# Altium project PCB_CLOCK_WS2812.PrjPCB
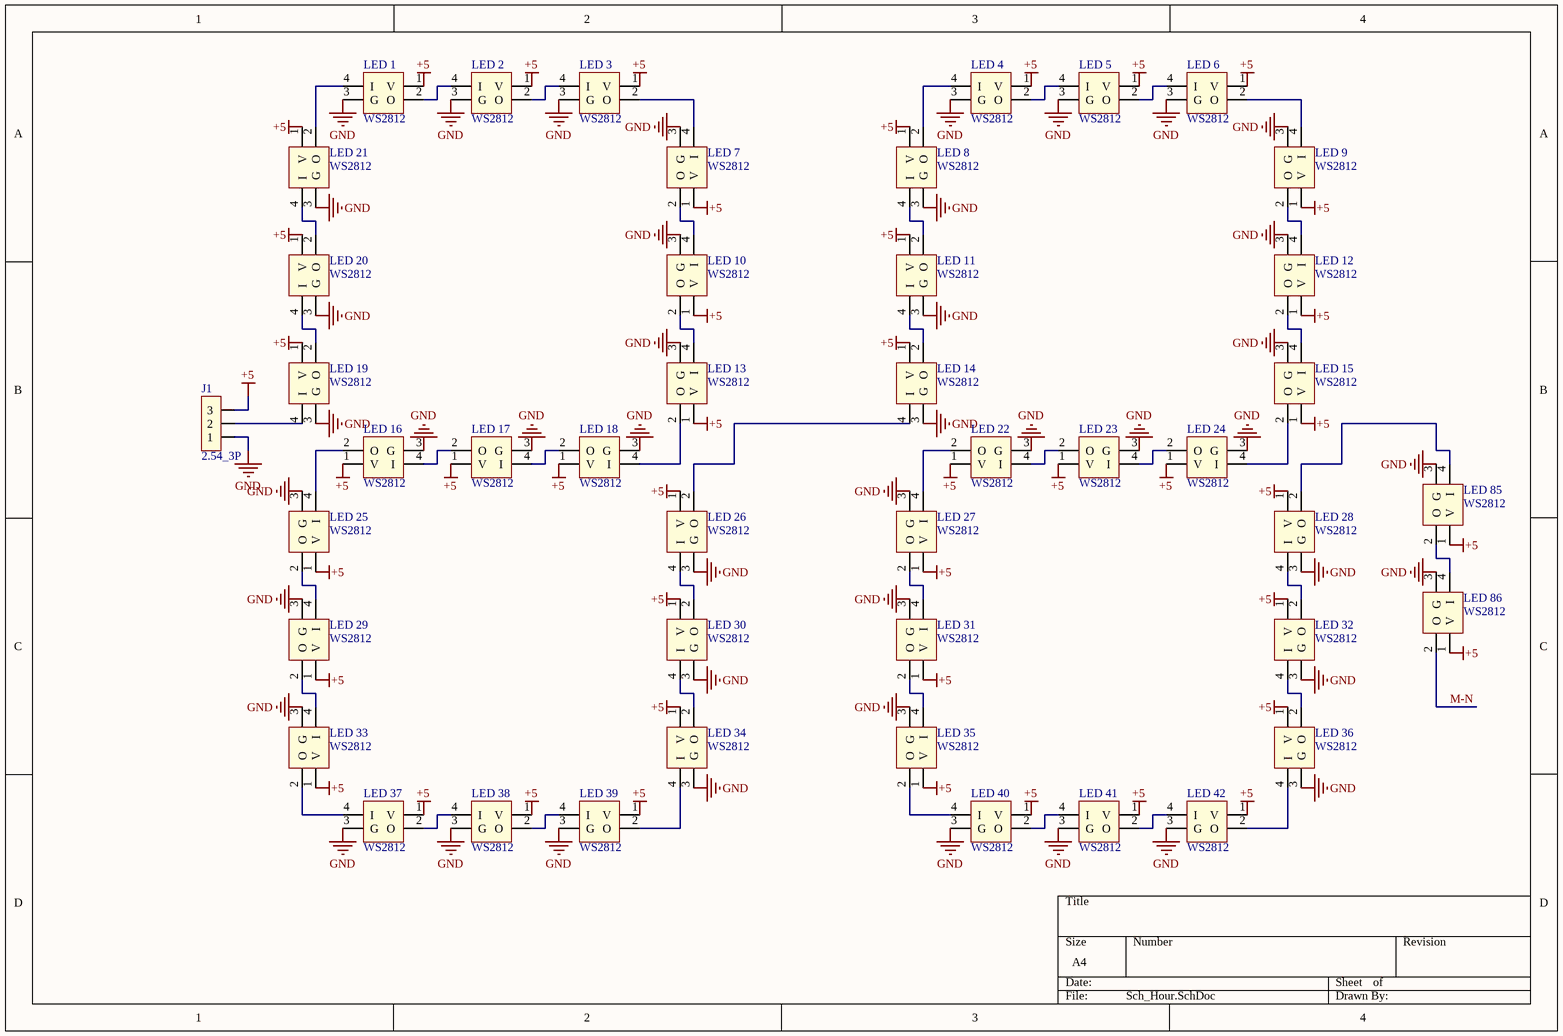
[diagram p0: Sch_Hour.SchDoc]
2 sheets, 88 parts. Net scope: global (net labels, ports and power ports of the same name join across sheets).
Board file: Clock WS2812.PcbDoc
Sheets:
  Sch_Hour.SchDoc
  Sch_Min.SchDoc

## Sheet Sch_Hour.SchDoc
size A4

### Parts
J1  2.54_3P  [jump don duc thang 2.54_3p]
LED_1  WS2812  [LED WS2812]
LED_2  WS2812  [LED WS2812]
LED_3  WS2812  [LED WS2812]
LED_4  WS2812  [LED WS2812]
LED_5  WS2812  [LED WS2812]
LED_6  WS2812  [LED WS2812]
LED_7  WS2812  [LED WS2812]
LED_8  WS2812  [LED WS2812]
LED_9  WS2812  [LED WS2812]
LED_10  WS2812  [LED WS2812]
LED_11  WS2812  [LED WS2812]
LED_12  WS2812  [LED WS2812]
LED_13  WS2812  [LED WS2812]
LED_14  WS2812  [LED WS2812]
LED_15  WS2812  [LED WS2812]
LED_16  WS2812  [LED WS2812]
LED_17  WS2812  [LED WS2812]
LED_18  WS2812  [LED WS2812]
LED_19  WS2812  [LED WS2812]
LED_20  WS2812  [LED WS2812]
LED_21  WS2812  [LED WS2812]
LED_22  WS2812  [LED WS2812]
LED_23  WS2812  [LED WS2812]
LED_24  WS2812  [LED WS2812]
LED_25  WS2812  [LED WS2812]
LED_26  WS2812  [LED WS2812]
LED_27  WS2812  [LED WS2812]
LED_28  WS2812  [LED WS2812]
LED_29  WS2812  [LED WS2812]
LED_30  WS2812  [LED WS2812]
LED_31  WS2812  [LED WS2812]
LED_32  WS2812  [LED WS2812]
LED_33  WS2812  [LED WS2812]
LED_34  WS2812  [LED WS2812]
LED_35  WS2812  [LED WS2812]
LED_36  WS2812  [LED WS2812]
LED_37  WS2812  [LED WS2812]
LED_38  WS2812  [LED WS2812]
LED_39  WS2812  [LED WS2812]
LED_40  WS2812  [LED WS2812]
LED_41  WS2812  [LED WS2812]
LED_42  WS2812  [LED WS2812]
LED_85  WS2812  [LED WS2812]
LED_86  WS2812  [LED WS2812]

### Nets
+5: J1.3 LED_1.1(V) LED_2.1(V) LED_3.1(V) LED_4.1(V) LED_5.1(V) LED_6.1(V) LED_7.1(V) LED_8.1(V) LED_9.1(V) LED_10.1(V) LED_11.1(V) LED_12.1(V) LED_13.1(V) LED_14.1(V) LED_15.1(V) LED_16.1(V) LED_17.1(V) LED_18.1(V) LED_19.1(V) LED_20.1(V) LED_21.1(V) LED_22.1(V) LED_23.1(V) LED_24.1(V) LED_25.1(V) LED_26.1(V) LED_27.1(V) LED_28.1(V) LED_29.1(V) LED_30.1(V) LED_31.1(V) LED_32.1(V) LED_33.1(V) LED_34.1(V) LED_35.1(V) LED_36.1(V) LED_37.1(V) LED_38.1(V) LED_39.1(V) LED_40.1(V) LED_41.1(V) LED_42.1(V) LED_85.1(V) LED_86.1(V)
GND: J1.1 LED_1.3(G) LED_2.3(G) LED_3.3(G) LED_4.3(G) LED_5.3(G) LED_6.3(G) LED_7.3(G) LED_8.3(G) LED_9.3(G) LED_10.3(G) LED_11.3(G) LED_12.3(G) LED_13.3(G) LED_14.3(G) LED_15.3(G) LED_16.3(G) LED_17.3(G) LED_18.3(G) LED_19.3(G) LED_20.3(G) LED_21.3(G) LED_22.3(G) LED_23.3(G) LED_24.3(G) LED_25.3(G) LED_26.3(G) LED_27.3(G) LED_28.3(G) LED_29.3(G) LED_30.3(G) LED_31.3(G) LED_32.3(G) LED_33.3(G) LED_34.3(G) LED_35.3(G) LED_36.3(G) LED_37.3(G) LED_38.3(G) LED_39.3(G) LED_40.3(G) LED_41.3(G) LED_42.3(G) LED_85.3(G) LED_86.3(G)
M-N: LED_86.2(O)
NetJ1_2: J1.2 LED_19.4(I)
NetLED_1_2: LED_1.2(O) LED_2.4(I)
NetLED_1_4: LED_1.4(I) LED_21.2(O)
NetLED_2_2: LED_2.2(O) LED_3.4(I)
NetLED_3_2: LED_3.2(O) LED_7.4(I)
NetLED_4_2: LED_4.2(O) LED_5.4(I)
NetLED_4_4: LED_4.4(I) LED_8.2(O)
NetLED_5_2: LED_5.2(O) LED_6.4(I)
NetLED_6_2: LED_6.2(O) LED_9.4(I)
NetLED_7_2: LED_7.2(O) LED_10.4(I)
NetLED_8_4: LED_8.4(I) LED_11.2(O)
NetLED_9_2: LED_9.2(O) LED_12.4(I)
NetLED_10_2: LED_10.2(O) LED_13.4(I)
NetLED_11_4: LED_11.4(I) LED_14.2(O)
NetLED_12_2: LED_12.2(O) LED_15.4(I)
NetLED_13_2: LED_13.2(O) LED_18.4(I)
NetLED_14_4: LED_14.4(I) LED_26.2(O)
NetLED_15_2: LED_15.2(O) LED_24.4(I)
NetLED_16_2: LED_16.2(O) LED_25.4(I)
NetLED_16_4: LED_16.4(I) LED_17.2(O)
NetLED_17_4: LED_17.4(I) LED_18.2(O)
NetLED_19_2: LED_19.2(O) LED_20.4(I)
NetLED_20_2: LED_20.2(O) LED_21.4(I)
NetLED_22_2: LED_22.2(O) LED_27.4(I)
NetLED_22_4: LED_22.4(I) LED_23.2(O)
NetLED_23_4: LED_23.4(I) LED_24.2(O)
NetLED_25_2: LED_25.2(O) LED_29.4(I)
NetLED_26_4: LED_26.4(I) LED_30.2(O)
NetLED_27_2: LED_27.2(O) LED_31.4(I)
NetLED_28_2: LED_28.2(O) LED_85.4(I)
NetLED_28_4: LED_28.4(I) LED_32.2(O)
NetLED_29_2: LED_29.2(O) LED_33.4(I)
NetLED_30_4: LED_30.4(I) LED_34.2(O)
NetLED_31_2: LED_31.2(O) LED_35.4(I)
NetLED_32_4: LED_32.4(I) LED_36.2(O)
NetLED_33_2: LED_33.2(O) LED_37.4(I)
NetLED_34_4: LED_34.4(I) LED_39.2(O)
NetLED_35_2: LED_35.2(O) LED_40.4(I)
NetLED_36_4: LED_36.4(I) LED_42.2(O)
NetLED_37_2: LED_37.2(O) LED_38.4(I)
NetLED_38_2: LED_38.2(O) LED_39.4(I)
NetLED_40_2: LED_40.2(O) LED_41.4(I)
NetLED_41_2: LED_41.2(O) LED_42.4(I)
NetLED_85_2: LED_85.2(O) LED_86.4(I)

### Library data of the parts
J1 = Jump Don Duc Thang 2.54_3P: Cắm; Ten_Linh_Kien: Jump Đơn Đực 2.54MM 1x40P Thẳng 11MM; Ma_Hang: MH000903; Don_Vi: Con; So_Chan: 2
LED_1-LED_42 LED_85 LED_86 = LED WS2812

## Sheet Sch_Min.SchDoc
size A4
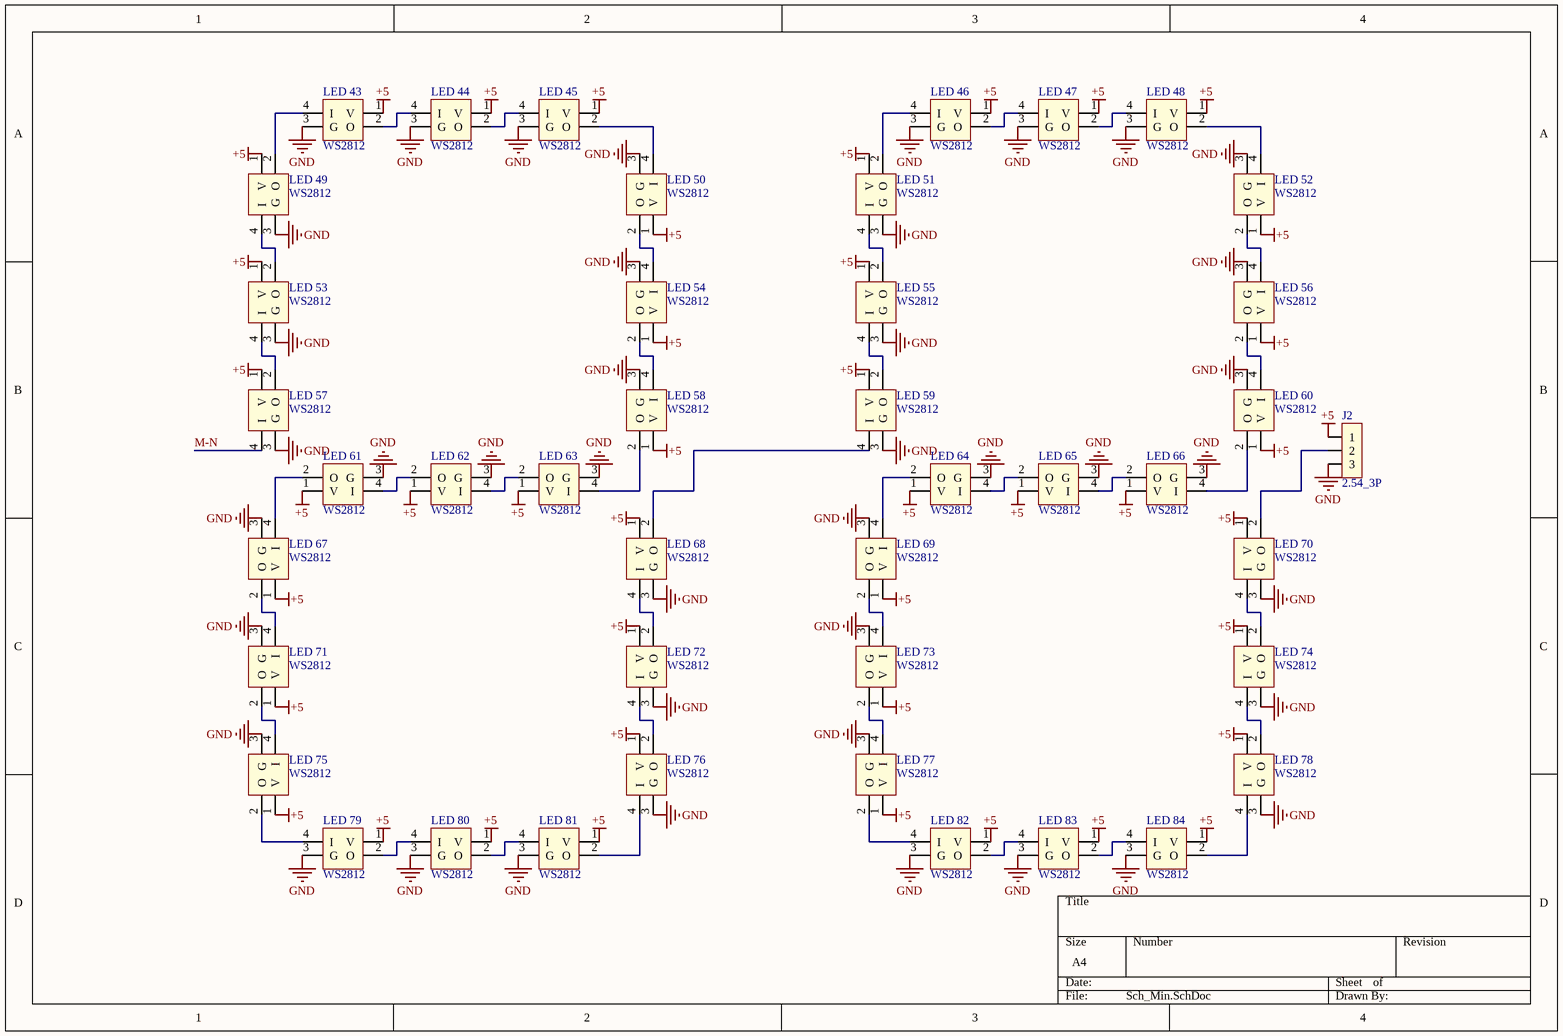
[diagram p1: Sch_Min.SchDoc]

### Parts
J2  2.54_3P  [jump don duc thang 2.54_3p]
LED_43  WS2812  [LED WS2812]
LED_44  WS2812  [LED WS2812]
LED_45  WS2812  [LED WS2812]
LED_46  WS2812  [LED WS2812]
LED_47  WS2812  [LED WS2812]
LED_48  WS2812  [LED WS2812]
LED_49  WS2812  [LED WS2812]
LED_50  WS2812  [LED WS2812]
LED_51  WS2812  [LED WS2812]
LED_52  WS2812  [LED WS2812]
LED_53  WS2812  [LED WS2812]
LED_54  WS2812  [LED WS2812]
LED_55  WS2812  [LED WS2812]
LED_56  WS2812  [LED WS2812]
LED_57  WS2812  [LED WS2812]
LED_58  WS2812  [LED WS2812]
LED_59  WS2812  [LED WS2812]
LED_60  WS2812  [LED WS2812]
LED_61  WS2812  [LED WS2812]
LED_62  WS2812  [LED WS2812]
LED_63  WS2812  [LED WS2812]
LED_64  WS2812  [LED WS2812]
LED_65  WS2812  [LED WS2812]
LED_66  WS2812  [LED WS2812]
LED_67  WS2812  [LED WS2812]
LED_68  WS2812  [LED WS2812]
LED_69  WS2812  [LED WS2812]
LED_70  WS2812  [LED WS2812]
LED_71  WS2812  [LED WS2812]
LED_72  WS2812  [LED WS2812]
LED_73  WS2812  [LED WS2812]
LED_74  WS2812  [LED WS2812]
LED_75  WS2812  [LED WS2812]
LED_76  WS2812  [LED WS2812]
LED_77  WS2812  [LED WS2812]
LED_78  WS2812  [LED WS2812]
LED_79  WS2812  [LED WS2812]
LED_80  WS2812  [LED WS2812]
LED_81  WS2812  [LED WS2812]
LED_82  WS2812  [LED WS2812]
LED_83  WS2812  [LED WS2812]
LED_84  WS2812  [LED WS2812]

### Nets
+5: J2.1 LED_43.1(V) LED_44.1(V) LED_45.1(V) LED_46.1(V) LED_47.1(V) LED_48.1(V) LED_49.1(V) LED_50.1(V) LED_51.1(V) LED_52.1(V) LED_53.1(V) LED_54.1(V) LED_55.1(V) LED_56.1(V) LED_57.1(V) LED_58.1(V) LED_59.1(V) LED_60.1(V) LED_61.1(V) LED_62.1(V) LED_63.1(V) LED_64.1(V) LED_65.1(V) LED_66.1(V) LED_67.1(V) LED_68.1(V) LED_69.1(V) LED_70.1(V) LED_71.1(V) LED_72.1(V) LED_73.1(V) LED_74.1(V) LED_75.1(V) LED_76.1(V) LED_77.1(V) LED_78.1(V) LED_79.1(V) LED_80.1(V) LED_81.1(V) LED_82.1(V) LED_83.1(V) LED_84.1(V)
GND: J2.3 LED_43.3(G) LED_44.3(G) LED_45.3(G) LED_46.3(G) LED_47.3(G) LED_48.3(G) LED_49.3(G) LED_50.3(G) LED_51.3(G) LED_52.3(G) LED_53.3(G) LED_54.3(G) LED_55.3(G) LED_56.3(G) LED_57.3(G) LED_58.3(G) LED_59.3(G) LED_60.3(G) LED_61.3(G) LED_62.3(G) LED_63.3(G) LED_64.3(G) LED_65.3(G) LED_66.3(G) LED_67.3(G) LED_68.3(G) LED_69.3(G) LED_70.3(G) LED_71.3(G) LED_72.3(G) LED_73.3(G) LED_74.3(G) LED_75.3(G) LED_76.3(G) LED_77.3(G) LED_78.3(G) LED_79.3(G) LED_80.3(G) LED_81.3(G) LED_82.3(G) LED_83.3(G) LED_84.3(G)
M-N: LED_57.4(I)
NetJ2_2: J2.2 LED_70.2(O)
NetLED_43_2: LED_43.2(O) LED_44.4(I)
NetLED_43_4: LED_43.4(I) LED_49.2(O)
NetLED_44_2: LED_44.2(O) LED_45.4(I)
NetLED_45_2: LED_45.2(O) LED_50.4(I)
NetLED_46_2: LED_46.2(O) LED_47.4(I)
NetLED_46_4: LED_46.4(I) LED_51.2(O)
NetLED_47_2: LED_47.2(O) LED_48.4(I)
NetLED_48_2: LED_48.2(O) LED_52.4(I)
NetLED_49_4: LED_49.4(I) LED_53.2(O)
NetLED_50_2: LED_50.2(O) LED_54.4(I)
NetLED_51_4: LED_51.4(I) LED_55.2(O)
NetLED_52_2: LED_52.2(O) LED_56.4(I)
NetLED_53_4: LED_53.4(I) LED_57.2(O)
NetLED_54_2: LED_54.2(O) LED_58.4(I)
NetLED_55_4: LED_55.4(I) LED_59.2(O)
NetLED_56_2: LED_56.2(O) LED_60.4(I)
NetLED_58_2: LED_58.2(O) LED_63.4(I)
NetLED_59_4: LED_59.4(I) LED_68.2(O)
NetLED_60_2: LED_60.2(O) LED_66.4(I)
NetLED_61_2: LED_61.2(O) LED_67.4(I)
NetLED_61_4: LED_61.4(I) LED_62.2(O)
NetLED_62_4: LED_62.4(I) LED_63.2(O)
NetLED_64_2: LED_64.2(O) LED_69.4(I)
NetLED_64_4: LED_64.4(I) LED_65.2(O)
NetLED_65_4: LED_65.4(I) LED_66.2(O)
NetLED_67_2: LED_67.2(O) LED_71.4(I)
NetLED_68_4: LED_68.4(I) LED_72.2(O)
NetLED_69_2: LED_69.2(O) LED_73.4(I)
NetLED_70_4: LED_70.4(I) LED_74.2(O)
NetLED_71_2: LED_71.2(O) LED_75.4(I)
NetLED_72_4: LED_72.4(I) LED_76.2(O)
NetLED_73_2: LED_73.2(O) LED_77.4(I)
NetLED_74_4: LED_74.4(I) LED_78.2(O)
NetLED_75_2: LED_75.2(O) LED_79.4(I)
NetLED_76_4: LED_76.4(I) LED_81.2(O)
NetLED_77_2: LED_77.2(O) LED_82.4(I)
NetLED_78_4: LED_78.4(I) LED_84.2(O)
NetLED_79_2: LED_79.2(O) LED_80.4(I)
NetLED_80_2: LED_80.2(O) LED_81.4(I)
NetLED_82_2: LED_82.2(O) LED_83.4(I)
NetLED_83_2: LED_83.2(O) LED_84.4(I)

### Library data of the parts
J2 = Jump Don Duc Thang 2.54_3P: as J1 on sheet Sch_Hour
LED_43-LED_84 = LED WS2812

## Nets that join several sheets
+5: Sch_Hour (45 pins), Sch_Min (43 pins)
GND: Sch_Hour (45 pins), Sch_Min (43 pins)
M-N: Sch_Hour (LED_86.2), Sch_Min (LED_57.4)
